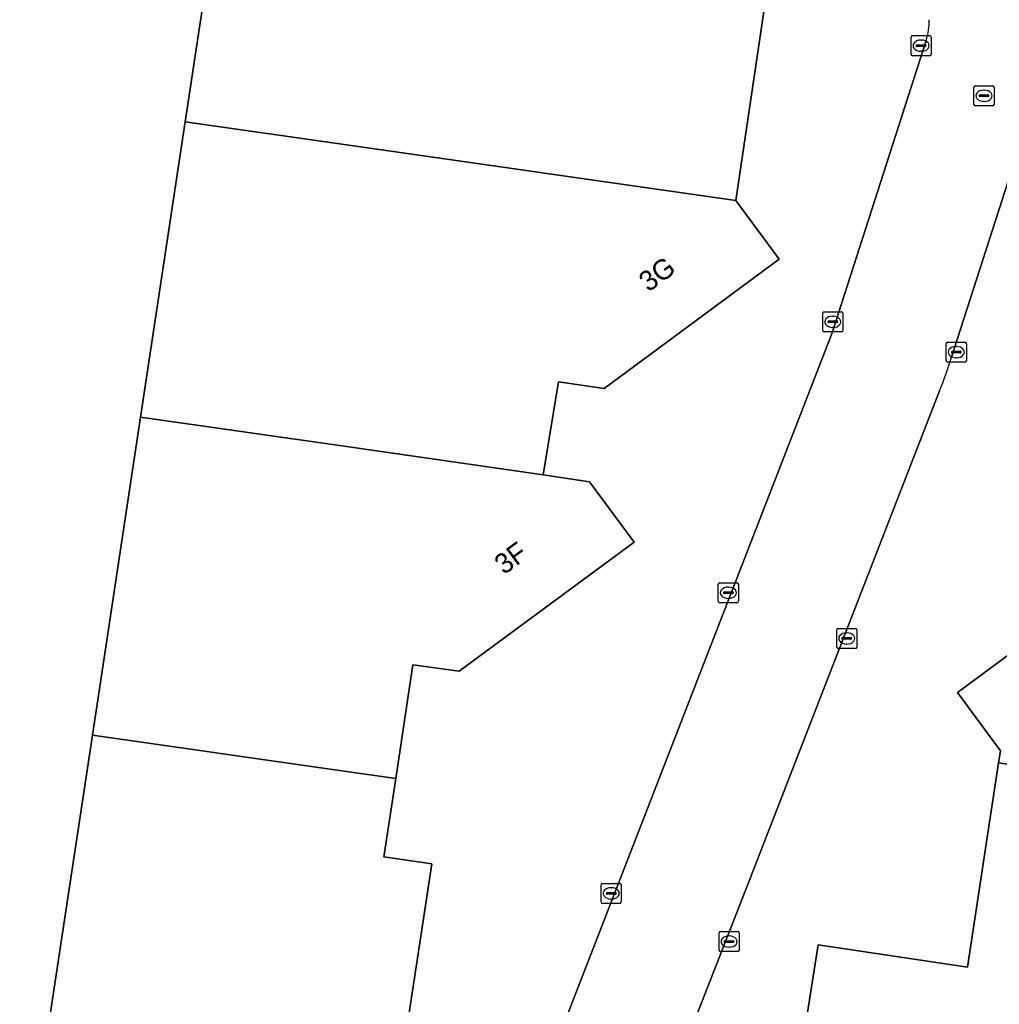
# Model space of a CAD drawing. Extents: x 163008 to 163854, y 382777 to 383982.
# Drawn here: x 163483.87 to 163532.58, y 382906.06 to 382955.05 of the extents above; entities that cross this region are included whole.
import ezdxf

# ---------------------------------------------------------------- set-up
doc = ezdxf.new("R2010")
doc.units = 0
for name, color, linetype in [('IMGEO_Erf', 7, 'Continuous'), ('IMGEO_Kolk', 7, 'Continuous'), ('IMGEO_Pand', 7, 'Continuous'), ('IMGEO_Pand_nummerreeks', 7, 'Continuous'), ('IMGEO_Rijbaan_lokaal_open', 7, 'Continuous'), ('IMGEO_Rioolput', 7, 'Continuous')]:
    doc.layers.add(name, color=color, linetype=linetype)

msp = doc.modelspace()

# ---------------------------------------------------------------- linework, layer by layer
at = {"layer": 'IMGEO_Erf'}
for points in [[(163538.481, 382967.309), (163537.742, 382964.703), (163534.61, 382951.947), (163530.187, 382938.199)], [(163483.866, 382895.556), (163485.843, 382908.616), (163487.483, 382919.451), (163489.878, 382935.27), (163492.101, 382949.958), (163494.406, 382965.186)], [(163520.921, 382955.792), (163519.476, 382946.042), (163521.632, 382943.129), (163512.928, 382936.702), (163510.664, 382937.025), (163509.898, 382932.406), (163512.205, 382932.056), (163514.43, 382929.049), (163505.728, 382922.624), (163503.415, 382922.95), (163502.567, 382917.295), (163501.982, 382913.389), (163504.359, 382913.04), (163501.317, 382892.985)], [(163510.309, 382903.495), (163524.27, 382939.463), (163528.938, 382954.013)], [(163529.612, 382936.585), (163520.091, 382912.069), (163516.194, 382902.096)], [(163522.95, 382905.012), (163523.569, 382909.018), (163530.996, 382907.897), (163532.548, 382918.079), (163532.638, 382918.67), (163530.507, 382921.57), (163539.097, 382927.913)]]:
    msp.add_lwpolyline(points, dxfattribs=at)
for centre, radius, start, end in [((163525.916, 382955.013), 3.183, 341.6892, 0.5935), ((163510.146, 382944.429), 20.987, 338.0517, 342.7306)]:
    msp.add_arc(centre, radius, start, end, dxfattribs=at)
at = {"layer": 'IMGEO_Kolk'}
for p, q in [((163528.192, 382953.326), (163528.192, 382954.178)), ((163528.267, 382954.252), (163529.119, 382954.252)), ((163528.68, 382954.032), (163528.705, 382954.032)), ((163529.193, 382954.178), (163529.193, 382953.326)), ((163528.451, 382953.746), (163528.451, 382953.758)), ((163528.889, 382953.709), (163528.491, 382953.709)), ((163528.494, 382953.795), (163528.892, 382953.795)), ((163528.703, 382953.472), (163528.678, 382953.472)), ((163528.935, 382953.758), (163528.935, 382953.746)), ((163529.119, 382953.252), (163528.267, 382953.252)), ((163523.801, 382939.589), (163523.801, 382940.441)), ((163523.876, 382940.515), (163524.728, 382940.515)), ((163524.289, 382940.295), (163524.314, 382940.295)), ((163524.802, 382940.441), (163524.802, 382939.589)), ((163524.06, 382940.009), (163524.06, 382940.021)), ((163524.498, 382939.972), (163524.1, 382939.972)), ((163524.103, 382940.058), (163524.501, 382940.058)), ((163524.312, 382939.735), (163524.287, 382939.735)), ((163524.544, 382940.021), (163524.544, 382940.009)), ((163524.728, 382939.515), (163523.876, 382939.515)), ((163529.942, 382938.08), (163529.942, 382938.932)), ((163530.017, 382939.006), (163530.869, 382939.006)), ((163530.43, 382938.786), (163530.455, 382938.786)), ((163530.943, 382938.932), (163530.943, 382938.08)), ((163530.201, 382938.5), (163530.201, 382938.512)), ((163530.639, 382938.463), (163530.241, 382938.463)), ((163530.244, 382938.549), (163530.642, 382938.549)), ((163530.453, 382938.226), (163530.428, 382938.226)), ((163530.685, 382938.512), (163530.685, 382938.5)), ((163530.869, 382938.006), (163530.017, 382938.006)), ((163518.608, 382926.107), (163518.608, 382926.959)), ((163518.683, 382927.033), (163519.535, 382927.033)), ((163519.609, 382926.959), (163519.609, 382926.107)), ((163518.867, 382926.527), (163518.867, 382926.539)), ((163519.305, 382926.49), (163518.907, 382926.49)), ((163518.91, 382926.576), (163519.308, 382926.576)), ((163519.096, 382926.813), (163519.121, 382926.813)), ((163519.351, 382926.539), (163519.351, 382926.527)), ((163519.535, 382926.033), (163518.683, 382926.033)), ((163519.119, 382926.253), (163519.094, 382926.253)), ((163524.495, 382923.834), (163524.495, 382924.686)), ((163524.57, 382924.76), (163525.422, 382924.76)), ((163524.983, 382924.54), (163525.008, 382924.54)), ((163525.496, 382924.686), (163525.496, 382923.834)), ((163524.754, 382924.254), (163524.754, 382924.266)), ((163525.192, 382924.217), (163524.794, 382924.217)), ((163524.797, 382924.303), (163525.195, 382924.303)), ((163525.238, 382924.266), (163525.238, 382924.254)), ((163525.422, 382923.76), (163524.57, 382923.76)), ((163525.006, 382923.98), (163524.981, 382923.98)), ((163512.783, 382911.149), (163512.783, 382912.001)), ((163512.858, 382912.075), (163513.71, 382912.075)), ((163513.271, 382911.855), (163513.296, 382911.855)), ((163513.784, 382912.001), (163513.784, 382911.149)), ((163513.042, 382911.569), (163513.042, 382911.581)), ((163513.48, 382911.532), (163513.082, 382911.532)), ((163513.085, 382911.618), (163513.483, 382911.618)), ((163513.294, 382911.295), (163513.269, 382911.295)), ((163513.526, 382911.581), (163513.526, 382911.569)), ((163513.71, 382911.075), (163512.858, 382911.075)), ((163518.643, 382908.753), (163518.643, 382909.605)), ((163518.718, 382909.679), (163519.57, 382909.679)), ((163519.131, 382909.459), (163519.156, 382909.459)), ((163519.644, 382909.605), (163519.644, 382908.753)), ((163518.902, 382909.173), (163518.902, 382909.185)), ((163519.34, 382909.136), (163518.942, 382909.136)), ((163518.945, 382909.222), (163519.343, 382909.222)), ((163519.154, 382908.899), (163519.129, 382908.899)), ((163519.386, 382909.185), (163519.386, 382909.173)), ((163519.57, 382908.679), (163518.718, 382908.679))]:
    msp.add_line(p, q, dxfattribs=at)
for points in [[(163528.192, 382953.326), (163528.192, 382954.178)], [(163528.267, 382954.252), (163529.119, 382954.252)], [(163529.193, 382954.178), (163529.193, 382953.326)], [(163529.119, 382953.252), (163528.267, 382953.252)], [(163523.801, 382939.589), (163523.801, 382940.441)], [(163523.876, 382940.515), (163524.728, 382940.515)], [(163524.802, 382940.441), (163524.802, 382939.589)], [(163524.728, 382939.515), (163523.876, 382939.515)], [(163529.942, 382938.08), (163529.942, 382938.932)], [(163530.017, 382939.006), (163530.869, 382939.006)], [(163530.943, 382938.932), (163530.943, 382938.08)], [(163530.869, 382938.006), (163530.017, 382938.006)], [(163518.608, 382926.107), (163518.608, 382926.959)], [(163518.683, 382927.033), (163519.535, 382927.033)], [(163519.609, 382926.959), (163519.609, 382926.107)], [(163519.535, 382926.033), (163518.683, 382926.033)], [(163524.495, 382923.834), (163524.495, 382924.686)], [(163524.57, 382924.76), (163525.422, 382924.76)], [(163525.496, 382924.686), (163525.496, 382923.834)], [(163525.422, 382923.76), (163524.57, 382923.76)], [(163512.783, 382911.149), (163512.783, 382912.001)], [(163512.858, 382912.075), (163513.71, 382912.075)], [(163513.784, 382912.001), (163513.784, 382911.149)], [(163513.71, 382911.075), (163512.858, 382911.075)], [(163518.643, 382908.753), (163518.643, 382909.605)], [(163518.718, 382909.679), (163519.57, 382909.679)], [(163519.644, 382909.605), (163519.644, 382908.753)], [(163519.57, 382908.679), (163518.718, 382908.679)]]:
    msp.add_lwpolyline(points, dxfattribs=at)
for centre, radius, start, end in [((163528.269, 382954.176), 0.0765, 91.552, 178.448), ((163528.269, 382954.176), 0.0765, 91.552, 178.448), ((163529.117, 382954.176), 0.0765, 1.552, 88.448), ((163529.117, 382954.176), 0.0765, 1.552, 88.448), ((163528.491, 382953.755), 0.0403, 85.8775, 175.7526), ((163528.488, 382953.745), 0.0366, 178.938, 274.7102), ((163528.892, 382953.752), 0.043, 264.8664, 352.4533), ((163528.896, 382953.757), 0.0386, 1.7309, 96.639), ((163528.269, 382953.328), 0.0765, 181.552, 268.448), ((163528.269, 382953.328), 0.0765, 181.552, 268.448), ((163529.117, 382953.328), 0.0765, 271.552, 358.448), ((163529.117, 382953.328), 0.0765, 271.552, 358.448), ((163523.878, 382940.439), 0.0765, 91.552, 178.448), ((163523.878, 382940.439), 0.0765, 91.552, 178.448), ((163524.726, 382940.439), 0.0765, 1.552, 88.448), ((163524.726, 382940.439), 0.0765, 1.552, 88.448), ((163524.1, 382940.018), 0.0403, 85.8775, 175.7526), ((163524.097, 382940.008), 0.0366, 178.938, 274.7102), ((163524.501, 382940.015), 0.043, 264.8664, 352.4533), ((163524.505, 382940.02), 0.0386, 1.7309, 96.639), ((163523.878, 382939.591), 0.0765, 181.552, 268.448), ((163523.878, 382939.591), 0.0765, 181.552, 268.448), ((163524.726, 382939.591), 0.0765, 271.552, 358.448), ((163524.726, 382939.591), 0.0765, 271.552, 358.448), ((163530.019, 382938.93), 0.0765, 91.552, 178.448), ((163530.019, 382938.93), 0.0765, 91.552, 178.448), ((163530.867, 382938.93), 0.0765, 1.552, 88.448), ((163530.867, 382938.93), 0.0765, 1.552, 88.448), ((163530.241, 382938.509), 0.0403, 85.8775, 175.7526), ((163530.238, 382938.499), 0.0366, 178.938, 274.7102), ((163530.642, 382938.506), 0.043, 264.8664, 352.4533), ((163530.646, 382938.511), 0.0386, 1.7309, 96.639), ((163530.019, 382938.082), 0.0765, 181.552, 268.448), ((163530.019, 382938.082), 0.0765, 181.552, 268.448), ((163530.867, 382938.082), 0.0765, 271.552, 358.448), ((163530.867, 382938.082), 0.0765, 271.552, 358.448), ((163518.685, 382926.957), 0.0765, 91.552, 178.448), ((163518.685, 382926.957), 0.0765, 91.552, 178.448), ((163519.533, 382926.957), 0.0765, 1.552, 88.448), ((163519.533, 382926.957), 0.0765, 1.552, 88.448), ((163518.907, 382926.536), 0.0403, 85.8775, 175.7526), ((163518.904, 382926.526), 0.0366, 178.938, 274.7102), ((163519.308, 382926.533), 0.043, 264.8664, 352.4533), ((163519.312, 382926.538), 0.0386, 1.7309, 96.639), ((163518.685, 382926.109), 0.0765, 181.552, 268.448), ((163518.685, 382926.109), 0.0765, 181.552, 268.448), ((163519.533, 382926.109), 0.0765, 271.552, 358.448), ((163519.533, 382926.109), 0.0765, 271.552, 358.448), ((163524.572, 382924.684), 0.0765, 91.552, 178.448), ((163524.572, 382924.684), 0.0765, 91.552, 178.448), ((163525.42, 382924.684), 0.0765, 1.552, 88.448), ((163525.42, 382924.684), 0.0765, 1.552, 88.448), ((163524.794, 382924.263), 0.0403, 85.8775, 175.7526), ((163524.791, 382924.253), 0.0366, 178.938, 274.7102), ((163525.195, 382924.26), 0.043, 264.8664, 352.4533), ((163525.199, 382924.265), 0.0386, 1.7309, 96.639), ((163524.572, 382923.836), 0.0765, 181.552, 268.448), ((163524.572, 382923.836), 0.0765, 181.552, 268.448), ((163525.42, 382923.836), 0.0765, 271.552, 358.448), ((163525.42, 382923.836), 0.0765, 271.552, 358.448), ((163512.86, 382911.999), 0.0765, 91.552, 178.448), ((163512.86, 382911.999), 0.0765, 91.552, 178.448), ((163513.708, 382911.999), 0.0765, 1.552, 88.448), ((163513.708, 382911.999), 0.0765, 1.552, 88.448), ((163513.082, 382911.578), 0.0403, 85.8775, 175.7526), ((163513.079, 382911.568), 0.0366, 178.938, 274.7102), ((163513.483, 382911.575), 0.043, 264.8664, 352.4533), ((163513.487, 382911.58), 0.0386, 1.7309, 96.639), ((163512.86, 382911.151), 0.0765, 181.552, 268.448), ((163512.86, 382911.151), 0.0765, 181.552, 268.448), ((163513.708, 382911.151), 0.0765, 271.552, 358.448), ((163513.708, 382911.151), 0.0765, 271.552, 358.448), ((163518.72, 382909.603), 0.0765, 91.552, 178.448), ((163518.72, 382909.603), 0.0765, 91.552, 178.448), ((163519.568, 382909.603), 0.0765, 1.552, 88.448), ((163519.568, 382909.603), 0.0765, 1.552, 88.448), ((163518.942, 382909.182), 0.0403, 85.8775, 175.7526), ((163518.939, 382909.172), 0.0366, 178.938, 274.7102), ((163519.343, 382909.179), 0.043, 264.8664, 352.4533), ((163519.347, 382909.184), 0.0386, 1.7309, 96.639), ((163518.72, 382908.755), 0.0765, 181.552, 268.448), ((163518.72, 382908.755), 0.0765, 181.552, 268.448), ((163519.568, 382908.755), 0.0765, 271.552, 358.448), ((163519.568, 382908.755), 0.0765, 271.552, 358.448)]:
    msp.add_arc(centre, radius, start, end, dxfattribs=at)
for centre, major_axis, ratio, start_param, end_param in [((163528.679, 382953.752), (-0.387, 0.002), 0.722429, 4.712389, 7.853982), ((163528.704, 382953.752), (-0.39, 0.002), 0.717154, 1.570796, 4.712389), ((163524.288, 382940.015), (-0.387, 0.002), 0.722429, 4.712389, 7.853982), ((163524.313, 382940.015), (-0.39, 0.002), 0.717154, 1.570796, 4.712389), ((163530.429, 382938.506), (-0.387, 0.002), 0.722429, 4.712389, 7.853982), ((163530.454, 382938.506), (-0.39, 0.002), 0.717154, 1.570796, 4.712389), ((163519.095, 382926.533), (-0.387, 0.002), 0.722429, 4.712389, 7.853982), ((163519.12, 382926.533), (-0.39, 0.002), 0.717154, 1.570796, 4.712389), ((163524.982, 382924.26), (-0.387, 0.002), 0.722429, 4.712389, 7.853982), ((163525.007, 382924.26), (-0.39, 0.002), 0.717154, 1.570796, 4.712389), ((163513.27, 382911.575), (-0.387, 0.002), 0.722429, 4.712389, 7.853982), ((163513.295, 382911.575), (-0.39, 0.002), 0.717154, 1.570796, 4.712389), ((163519.13, 382909.179), (-0.387, 0.002), 0.722429, 4.712389, 7.853982), ((163519.155, 382909.179), (-0.39, 0.002), 0.717154, 1.570796, 4.712389)]:
    msp.add_ellipse(centre, major_axis=major_axis, ratio=ratio, start_param=start_param, end_param=end_param, dxfattribs=at)
at = {"layer": 'IMGEO_Pand'}
for points in [[(163519.476, 382946.042), (163520.921, 382955.792), (163523.871, 382957.967), (163517.576, 382966.506), (163514.664, 382966.942), (163514.306, 382964.626), (163509.783, 382965.369), (163510.194, 382967.614), (163500, 382969.162), (163495.414, 382969.858), (163495.45, 382970.082), (163495.154, 382970.129), (163494.406, 382965.186), (163492.101, 382949.958), (163500, 382948.828)], [(163489.878, 382935.27), (163500, 382933.822), (163509.898, 382932.406), (163510.664, 382937.025), (163512.928, 382936.702), (163521.632, 382943.129), (163519.476, 382946.042), (163500, 382948.828), (163492.101, 382949.958)], [(163489.878, 382935.27), (163487.483, 382919.451), (163500, 382917.662), (163502.567, 382917.295), (163503.415, 382922.95), (163505.728, 382922.624), (163514.43, 382929.049), (163512.205, 382932.056), (163509.898, 382932.406), (163500, 382933.822)], [(163539.642, 382931.509), (163539.097, 382927.913), (163530.507, 382921.57), (163532.638, 382918.67), (163532.548, 382918.079), (163555.636, 382914.537), (163557.811, 382928.723)], [(163504.359, 382913.04), (163501.982, 382913.389), (163502.567, 382917.295), (163500, 382917.662), (163487.483, 382919.451), (163485.843, 382908.616), (163483.866, 382895.556), (163498.92, 382893.326), (163500, 382893.172), (163501.317, 382892.985)], [(163555.636, 382914.537), (163532.548, 382918.079), (163530.996, 382907.897), (163523.569, 382909.018), (163522.95, 382905.012), (163553.464, 382900.371)]]:
    msp.add_lwpolyline(points, close=True, dxfattribs=at)
at = {"layer": 'IMGEO_Rijbaan_lokaal_open'}
for points in [[(163530.187, 382938.199), (163534.61, 382951.947), (163537.742, 382964.703), (163538.481, 382967.309)], [(163528.938, 382954.013), (163524.27, 382939.463), (163510.309, 382903.495)], [(163516.194, 382902.096), (163520.091, 382912.069), (163529.612, 382936.585)]]:
    msp.add_lwpolyline(points, dxfattribs=at)
for centre, radius, start, end in [((163525.916, 382955.013), 3.183, 341.6892, 0.5935), ((163510.146, 382944.429), 20.987, 338.0517, 342.7306)]:
    msp.add_arc(centre, radius, start, end, dxfattribs=at)
at = {"layer": 'IMGEO_Rioolput'}
for p, q in [((163531.322, 382950.834), (163531.322, 382951.686)), ((163531.397, 382951.76), (163532.249, 382951.76)), ((163531.81, 382951.54), (163531.835, 382951.54)), ((163532.323, 382951.686), (163532.323, 382950.834)), ((163531.581, 382951.254), (163531.581, 382951.266)), ((163532.019, 382951.217), (163531.621, 382951.217)), ((163531.624, 382951.303), (163532.022, 382951.303)), ((163531.833, 382950.98), (163531.808, 382950.98)), ((163532.065, 382951.266), (163532.065, 382951.254)), ((163532.249, 382950.76), (163531.397, 382950.76))]:
    msp.add_line(p, q, dxfattribs=at)
for points in [[(163531.322, 382950.834), (163531.322, 382951.686)], [(163531.397, 382951.76), (163532.249, 382951.76)], [(163532.323, 382951.686), (163532.323, 382950.834)], [(163532.249, 382950.76), (163531.397, 382950.76)]]:
    msp.add_lwpolyline(points, dxfattribs=at)
for centre, radius, start, end in [((163531.399, 382951.684), 0.0765, 91.552, 178.448), ((163531.399, 382951.684), 0.0765, 91.552, 178.448), ((163532.247, 382951.684), 0.0765, 1.552, 88.448), ((163532.247, 382951.684), 0.0765, 1.552, 88.448), ((163531.621, 382951.263), 0.0403, 85.8775, 175.7526), ((163531.618, 382951.253), 0.0366, 178.938, 274.7102), ((163532.022, 382951.26), 0.043, 264.8664, 352.4533), ((163532.026, 382951.265), 0.0386, 1.7309, 96.639), ((163531.399, 382950.836), 0.0765, 181.552, 268.448), ((163531.399, 382950.836), 0.0765, 181.552, 268.448), ((163532.247, 382950.836), 0.0765, 271.552, 358.448), ((163532.247, 382950.836), 0.0765, 271.552, 358.448)]:
    msp.add_arc(centre, radius, start, end, dxfattribs=at)
for centre, major_axis, ratio, start_param, end_param in [((163531.809, 382951.26), (-0.387, 0.002), 0.722429, 4.712389, 7.853982), ((163531.834, 382951.26), (-0.39, 0.002), 0.717154, 1.570796, 4.712389)]:
    msp.add_ellipse(centre, major_axis=major_axis, ratio=ratio, start_param=start_param, end_param=end_param, dxfattribs=at)

# ---------------------------------------------------------------- texts
at = {"layer": 'IMGEO_Pand_nummerreeks'}
for s, rotation, p in [('3G', 36.442, (163515.138, 382941.466)), ('3F', 36.4398, (163507.952, 382927.399))]:
    msp.add_text(s, height=1, rotation=rotation, dxfattribs=at).set_placement(p)

doc.saveas('drawing.dxf')
